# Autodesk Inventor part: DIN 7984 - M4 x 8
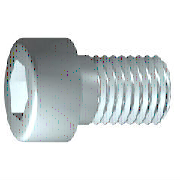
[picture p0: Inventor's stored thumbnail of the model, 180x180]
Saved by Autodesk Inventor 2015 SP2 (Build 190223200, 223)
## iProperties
IsCustomPart: 0
Created: 2012-02
Part Number: DIN 7984 - M4 x 8
Material: Stahl, weich
Description: Zylinderkopfschraube
Document SubType Name: Modeling
Standard: DIN 7984
Designer: rYan
Standard Revision: 1985
Standards Organization: DIN
Language: de-DE
Size Designation: M4 x 8
Categories: <MemberInstance><Categories><Category DisplayName="Verbindungselemente" InternalName="e4da775c-781d-43d5-af7c-5136215cf5a6" Mnemonic="FSTN"><Category DisplayNam
Density: 7.85 g/cm^3
Mass: 1.50945 g
Surface Area: 2.52684 cm^2
Volume: 0.192286 cm^3
Appearance: Halbpoliert
Author: rYan
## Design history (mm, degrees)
sketch "Skizze1"
  geometry: L1 (0.333, 0)-(8, 0); L2 (8, 0)-(8, 2); L3 (8, 2)-(2.1, 2); L4 (2.1, 2)-(1.67, 2); L5 (1.67, 2)-(0, 2); L6 (0, 2)-(0, 3.5); L7 (0, 3.5)-(-2.8, 3.5); L8 (-2.8, 3.5)-(-2.8, 1.443); L9 (-2.8, 1.443)-(-0.5, 1.443); L10 (-0.5, 1.443)-(0.333, 0); L11 (-4.96, 0)-(10.16, 0) reference; L12 (0, -0.7)-(0, 4.2) reference; L13 (2.1, 2)-(0, 2)
  constraints: 22 end point, 6 parallel, 2 collinear, 2 perpendicular, 1 horizontal, 1 point on line
  dimensions: "d1" = 5.9 distance from line of L3.end L2 (= GEL); "d2" = 0.42952 distance of L4.end L3.end (computed from GAL); "d3" = 2.8 distance between parallel lines of L8 L6 (= KOH); "d4" = 2.3 distance of L8.end L9.end (= INTI); "d5" = 60 deg angle of L10 L1; "d6" = 4 diameter of L3 L1 (= GD); "d7" = 4 diameter of L5 L1 (= BDM); "d8" = 2.88675 diameter of L9 L1 (= 1.1547 x SW); "d9" = 7 diameter of L7 L1 (= KOD); "d26" = 8 distance between parallel lines of L12 L2 (= NLG)
revolve "Körper" sketch "Skizze1" stored, may be unused: angle "d10" = 90 deg
sketch "Skizze2"
  geometry: L1 (0, -4.9)-(0, 4.9) reference; L2 (-4.9, 0)-(4.9, 0) reference; L3 (1.443, 0)-(0.722, -1.25); L4 (0.722, -1.25)-(-0.722, -1.25); L5 (-0.722, -1.25)-(-1.443, 0); L6 (-1.443, 0)-(-0.722, 1.25); L7 (-0.722, 1.25)-(0.722, 1.25); L8 (0.722, 1.25)-(1.443, 0); 2 further points
  constraints: 12 end point, 1 coincident, 1 horizontal alignment, 1 point on line, 12 other
extrude "Loch" join sketch "Skizze2" stored distance "d11" = 10; taper "d12" = 0 deg
workplane "Work Plane1"
fillet "Fillet2" dims "d30" = 0.1 (= R)
body "Solid1"
fillet "Rundung1" dims "d17" = 0.4 (= RR)
feature "Gewinde" dims "d13" = 5.9 (= GEL), "d14" = 0
chamfer "Fase1" distance "d15" = 0.42941 (= -0.5 x SPD + 0.5 x GD); stored, may be unused: second distance "d16" = 0.42941 (= GUL), angle "d27" = 45 deg
other parameters: "GD" = 4 (= NND) [user parameter; used in 2 equation terms], "NLG" = 8 [user parameter; used in 1 equation term], "GEL" = 5.9 [user parameter; used in 2 equation terms], "KOD" = 7 [user parameter; used in 1 equation term], "KOH" = 2.8 [user parameter; used in 1 equation term], "INTI" = 2.3 [user parameter; used in 1 equation term], "GAL" = 0.42941 (= 0.61345 x PTC) [user parameter; used in 1 equation term], "GUL" = 0.42941 (= 0.61345 x PTC) [user parameter; used in 1 equation term], "BDM" = 4 (= NND) [user parameter; used in 1 equation term], "SW" = 2.5 [user parameter; used in 2 equation terms], "RR" = 0.4 [user parameter; used in 1 equation term], "SPD" = 3.14117 (= NND - 1.2269 x PTC) [user parameter; used in 1 equation term], "d19" = 0, "d28" = 0, "d29" = 0, "R" = 0.1 [user parameter; used in 1 equation term], "TOA" = 30 deg [user parameter], "GD1" = 3.14117 (= THREADDIA - 1.2269 x PTC) [user parameter], "THREADDIA" = 4 [user parameter; used in 1 equation term], "FAWI" = 45 deg [user parameter], "ANG" = 120 deg [user parameter], "TPU" = 14.28571 (computed from PTC) [user parameter], "PTC" = 0.7 [user parameter; used in 5 equation terms], "NND" = 4 [user parameter; used in 3 equation terms], "E0" = 2.8875 (= 1.155 x SW) [user parameter]
